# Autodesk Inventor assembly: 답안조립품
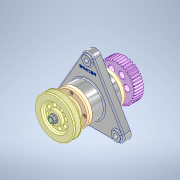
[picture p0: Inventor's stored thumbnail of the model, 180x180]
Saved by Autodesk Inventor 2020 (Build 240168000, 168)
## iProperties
Created: 2023-04
Part Number: 답안조립품
Document SubType Name: Assembly
Designer: oem
Author: oem
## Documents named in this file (11)
- C:\Users\oem\Desktop\730407V1011\답안조립품.iam
- C:\Users\oem\Desktop\730407V1011\6각 플랜지 너트 M10.ipt
- C:\Users\oem\Desktop\730407V1011\v-벨트풀리.ipt
- C:\Users\oem\Desktop\730407V1011\묻힘키 5x5x16.ipt
- C:\Users\oem\Desktop\730407V1011\베어링 6204.ipt
- C:\Users\oem\Desktop\730407V1011\본체.ipt
- C:\Users\oem\Desktop\730407V1011\볼트 M4 x 12.ipt
- C:\Users\oem\Desktop\730407V1011\스퍼기어.ipt
- C:\Users\oem\Desktop\730407V1011\오일 실 20 32 8.ipt
- C:\Users\oem\Desktop\730407V1011\축.ipt
- C:\Users\oem\Desktop\730407V1011\커버.ipt
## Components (3 placed, 2 different names)
1. 6각 플랜지 너트 M10:1
2. v-벨트풀리:1
3. 6각 플랜지 너트 M10:2
